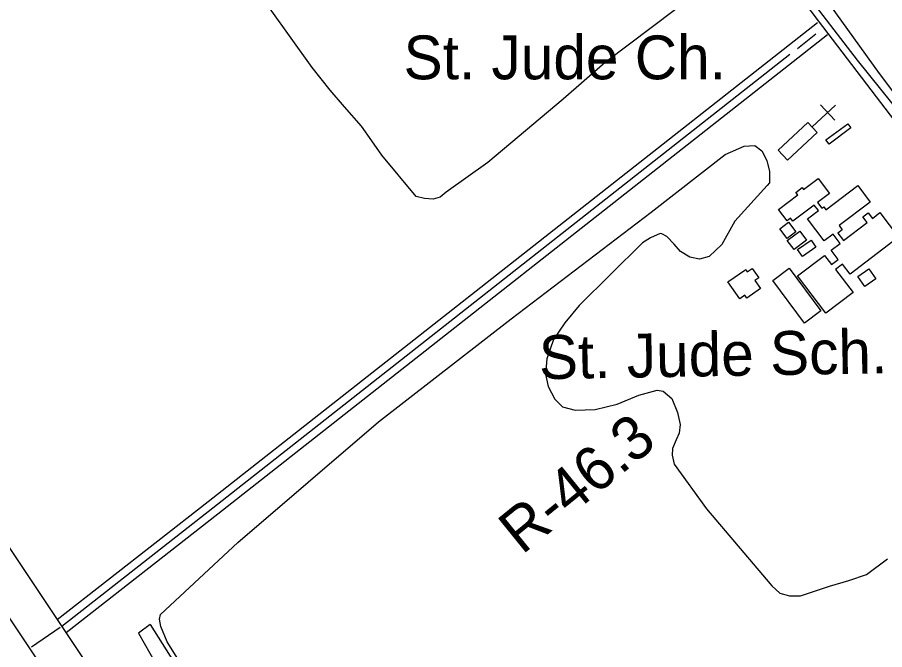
# Model space of a CAD drawing. Extents: x 3767014 to 3805179, y 361544 to 387384.
# Drawn here: x 3775133 to 3776776, y 382751 to 383949 of the extents above; entities that cross this region are included whole.
import ezdxf

# ---------------------------------------------------------------- set-up
doc = ezdxf.new("R2010")
doc.units = 0
for name, color, linetype in [('V-BLDG-IDEN', 7, 'Continuous'), ('V-BLDG-OTLN', 7, 'Continuous'), ('V-RIVR-EDGE', 7, 'Continuous'), ('V-RIVR-RANG-IDEN', 7, 'Continuous'), ('V-ROAD-CNTR', 7, 'Continuous'), ('V-SITE-OTLN', 7, 'Continuous'), ('V-SITE-VEGE', 7, 'Continuous'), ('V-TOPO-SHOR', 7, 'Continuous')]:
    doc.layers.add(name, color=color, linetype=linetype)

msp = doc.modelspace()

# ---------------------------------------------------------------- linework, layer by layer
at = {"layer": 'V-BLDG-OTLN'}
for points in [[(3776648.173, 383730.31), (3776591.923, 383678.231), (3776574.216, 383697.358), (3776630.466, 383749.434)], [(3776706.156, 383747.116), (3776711.966, 383739.288), (3776670.676, 383708.63), (3776664.866, 383716.453)], [(3776802.416, 383532.156), (3776710.578, 383462.364), (3776696.379, 383481.048), (3776683.159, 383471.002), (3776716.171, 383427.566), (3776664.606, 383388.38), (3776611.051, 383458.856), (3776662.2, 383497.723), (3776675.325, 383480.452), (3776688.115, 383490.17), (3776674.897, 383507.563), (3776691.769, 383520.386), (3776678.373, 383538.011), (3776661.7, 383525.34), (3776629.938, 383567.134), (3776650.412, 383582.694), (3776642.463, 383593.151), (3776601.88, 383562.31), (3776597.469, 383568.115), (3776591.253, 383563.388), (3776575.012, 383584.761), (3776611.274, 383612.319), (3776607.602, 383617.152), (3776619.71, 383626.356), (3776622.495, 383622.696), (3776649.805, 383643.45), (3776671.416, 383615.014), (3776649.068, 383598.032), (3776657.293, 383587.206), (3776660.486, 383589.633), (3776664.606, 383584.21), (3776724.875, 383630.007), (3776748.554, 383598.849), (3776689.663, 383554.096), (3776695.484, 383546.434), (3776687.157, 383540.104), (3776697.995, 383525.844), (3776742.813, 383559.906), (3776734.666, 383570.625), (3776744.867, 383578.377), (3776752.805, 383567.93), (3776767.021, 383578.733)], [(3776593.782, 383560.584), (3776607.6, 383542.564), (3776591.237, 383530.016), (3776577.419, 383548.038)], [(3776615.229, 383543.86), (3776628.168, 383526.749), (3776604.332, 383508.718), (3776591.39, 383525.832)], [(3776645.722, 383513.158), (3776620.107, 383495.689), (3776610.881, 383509.218), (3776636.495, 383526.688)], [(3776479.07, 383447.565), (3776512.825, 383471.048), (3776515.719, 383466.886), (3776524.797, 383473.202), (3776537.321, 383455.202), (3776530.155, 383450.215), (3776540.755, 383434.974), (3776514.785, 383416.909), (3776511.061, 383422.264), (3776501.362, 383415.518)], [(3776595.159, 383473.526), (3776655.273, 383392.689), (3776624.193, 383369.575), (3776564.076, 383450.412)], [(3776745.803, 383472.379), (3776759.052, 383453.168), (3776738.394, 383438.921), (3776725.172, 383458.145)]]:
    msp.add_lwpolyline(points, close=True, dxfattribs=at)
at = {"layer": 'V-RIVR-EDGE'}
msp.add_spline([(3776564.722, 385223.299), (3776600.731, 385181.098), (3776661.2, 385105.736), (3776715.203, 385032.007), (3776816.784, 384902.358), (3776846.605, 384861.038), (3776857.883, 384843.218), (3776882.888, 384816.468), (3776915.962, 384782.419), (3776954.66, 384732.99), (3776978.836, 384698.155), (3777017.529, 384647.108), (3777120.713, 384511.794), (3777150.55, 384476.944), (3777181.198, 384442.901), (3777207.8, 384408.06), (3777254.587, 384359.42), (3777285.235, 384325.377), (3777306.975, 384286.503), (3777352.136, 384234.632), (3777398.919, 384184.375), (3777453.759, 384121.966), (3777499.732, 384071.711), (3777554.576, 384010.92), (3777589.252, 383970.397), (3777621.507, 383932.306), (3777678.778, 383871.509), (3777722.335, 383825.304), (3777756.204, 383785.592), (3777794.915, 383741.824), (3777871.521, 383651.056), (3777927.937, 383571.66), (3777966.622, 383517.378), (3777996.431, 383471.207), (3778029.475, 383425.027), (3778067.358, 383373.174), (3778126.177, 383284.876), (3778156.015, 383250.026), (3778180.211, 383223.278), (3778202.787, 383195.725), (3778212.458, 383181.952), (3778217.257, 383160.105), (3778222.842, 383129.359), (3778231.692, 383110.736), (3778252.643, 383079.952), (3778272.805, 383057.257), (3778301.832, 383021.601), (3778314.725, 383002.968), (3778332.478, 382986.749), (3778341.366, 382983.492), (3778349.453, 382983.472), (3778360.791, 382989.914), (3778364.028, 382990.715), (3778372.922, 382989.884), (3778380.996, 382984.203), (3778411.652, 382953.395), (3778438.266, 382923.406), (3778460.048, 382901.516), (3778499.574, 382860.173), (3778541.506, 382810.736), (3778575.377, 382771.833), (3778604.389, 382730.515), (3778631.764, 382681.114), (3778646.24, 382647.92)], degree=3, dxfattribs=at)
at = {"layer": 'V-ROAD-CNTR'}
for points in [[(3775684.469, 385214.457), (3776649.742, 383941.706), (3777712.873, 382550.421)], [(3773625.9, 385186.349), (3774181.119, 384346.19), (3775216.704, 382795.428), (3776380.625, 381052.708), (3777283.017, 379696.102), (3777445.775, 379463.11), (3777569.907, 379293.951), (3777617.356, 379230.723), (3777830.706, 378985.678), (3778010.091, 378796.753), (3778274.944, 378542.232), (3778638.611, 378241.543), (3779057.65, 377959.067)], [(3773538.269, 385185.098), (3774135.962, 384280.668), (3775171.547, 382729.907), (3776335.468, 380987.186), (3777237.86, 379630.58), (3777400.618, 379397.588), (3777524.75, 379228.43), (3777572.199, 379165.201), (3777785.549, 378920.156), (3777964.934, 378731.232), (3778229.788, 378476.71), (3778593.454, 378176.022), (3779012.493, 377893.545)], [(3776648.833, 383938.278), (3775494.058, 383031.246), (3775208.351, 382807.937)], [(3776667.908, 383915.115), (3775512.56, 383007.632), (3775225.058, 382782.92)], [(3776645.678, 383916.727), (3776610.631, 383889.199)], [(3776596.222, 383877.881), (3775503.309, 383019.439), (3775216.704, 382795.428)], [(3775213.908, 382793.237), (3775159.579, 382755.886)]]:
    msp.add_lwpolyline(points, dxfattribs=at)
at = {"layer": 'V-SITE-OTLN'}
for p, q in [((3776638.894, 383740.947), (3776682.593, 383782.062)), ((3776681.732, 383753.79), (3776654.323, 383782.923))]:
    msp.add_line(p, q, dxfattribs=at)
at = {"layer": 'V-SITE-VEGE'}
for p, q in [((3775691.458, 383853.403), (3775611.787, 383964.618)), ((3776379.789, 383963.284), (3776246.636, 383863.35)), ((3776246.636, 383863.35), (3776166.897, 383793.552)), ((3775725.522, 383810.594), (3775691.458, 383853.403)), ((3775752.378, 383779.384), (3775725.522, 383810.594)), ((3776166.897, 383793.552), (3776024.102, 383673.55)), ((3775784.595, 383742.403), (3775752.378, 383779.384)), ((3775804.364, 383714.598), (3775784.595, 383742.403)), ((3775823.542, 383687.368), (3775804.364, 383714.598)), ((3775888.627, 383609.314), (3775823.542, 383687.368)), ((3776024.102, 383673.55), (3775945.324, 383617.24)), ((3775903.92, 383605.456), (3775888.627, 383609.314)), ((3775945.324, 383617.24), (3775933.751, 383608.268)), ((3775920.336, 383604.54), (3775903.92, 383605.456)), ((3775933.751, 383608.268), (3775920.336, 383604.54))]:
    msp.add_line(p, q, dxfattribs=at)
for points in [[(3776879.362, 383691.904), (3776766.363, 383842.512), (3776657.475, 383993.773)], [(3775596.29, 382479.451), (3775416.309, 382766.32), (3775404.316, 382794.988), (3775401.789, 382808.798), (3775403.95, 382818.067), (3775550.695, 382954.28), (3775817.183, 383182.415), (3776068.026, 383377.984), (3776333.778, 383579.561), (3776474.019, 383689.123), (3776509.556, 383704.69), (3776530.311, 383706.172), (3776543.166, 383695.986), (3776552.689, 383677.668), (3776557.633, 383656.969), (3776557.979, 383635.045), (3776553.437, 383630.355), (3776492.181, 383562.442), (3776467.486, 383518.19), (3776443.6, 383495.882), (3776425.209, 383490.975), (3776406.691, 383494.145), (3776389.201, 383505.411), (3776377.442, 383519.077), (3776363.358, 383533.858), (3776354.054, 383538.328), (3776350.572, 383539.426), (3776332.236, 383531.058), (3776317.382, 383521.588), (3776196.904, 383403.105), (3776169.717, 383370.358), (3776148.287, 383338.853), (3776136.177, 383301.727), (3776133.171, 383272.824), (3776138.151, 383249.816), (3776151.232, 383225.783), (3776165.312, 383211.003), (3776189.657, 383204.461), (3776227.719, 383206.217), (3776269.115, 383216.104), (3776310.403, 383232.916), (3776344.874, 383242.696), (3776356.452, 383240.57), (3776372.826, 383226.977), (3776383.631, 383200.601), (3776388.612, 383177.596), (3776386.557, 383161.402), (3776380.989, 383148.619), (3776374.321, 383132.353)], [(3776374.321, 383132.353), (3776373.366, 383119.641), (3776377.104, 383102.387), (3776438.458, 383017.944), (3776561.958, 382872.151), (3776577.179, 382858.542), (3776595.734, 382853.061), (3776616.505, 382853.393), (3776671.621, 382871.575), (3776708.382, 382882.544), (3776741.685, 382893.46), (3776781.617, 382922.947)]]:
    msp.add_lwpolyline(points, dxfattribs=at)
at = {"layer": 'V-TOPO-SHOR'}
for points in [[(3776620.865, 384002.02), (3776724.191, 383867.735), (3776856.831, 383702.728), (3776959.643, 383563.728), (3777085.153, 383403.314), (3777186.107, 383270.169), (3777304.444, 383116.705), (3777412.534, 382978.964)], [(3775384.563, 382798.775), (3775362.51, 382782.575), (3775469.418, 382593.453), (3775591.178, 382393.408), (3775614.273, 382355.813)], [(3775384.563, 382798.775), (3775470.682, 382662.165), (3775587.559, 382473.786), (3775648.485, 382370.829)]]:
    msp.add_lwpolyline(points, dxfattribs=at)

# ---------------------------------------------------------------- texts
at = {"layer": 'V-BLDG-IDEN'}
msp.add_text('St. Jude Ch.', height=83, dxfattribs=at).set_placement((3775864.5, 383831.209))
msp.add_text('St. Jude Sch.', height=83, rotation=1, dxfattribs=at).set_placement((3776121.524, 383263.305))
at = {"layer": 'V-RIVR-RANG-IDEN'}
msp.add_text('R-46.3', height=83, rotation=39.04948, dxfattribs=at).set_placement((3776088.799, 382929.735))

doc.saveas('drawing.dxf')
